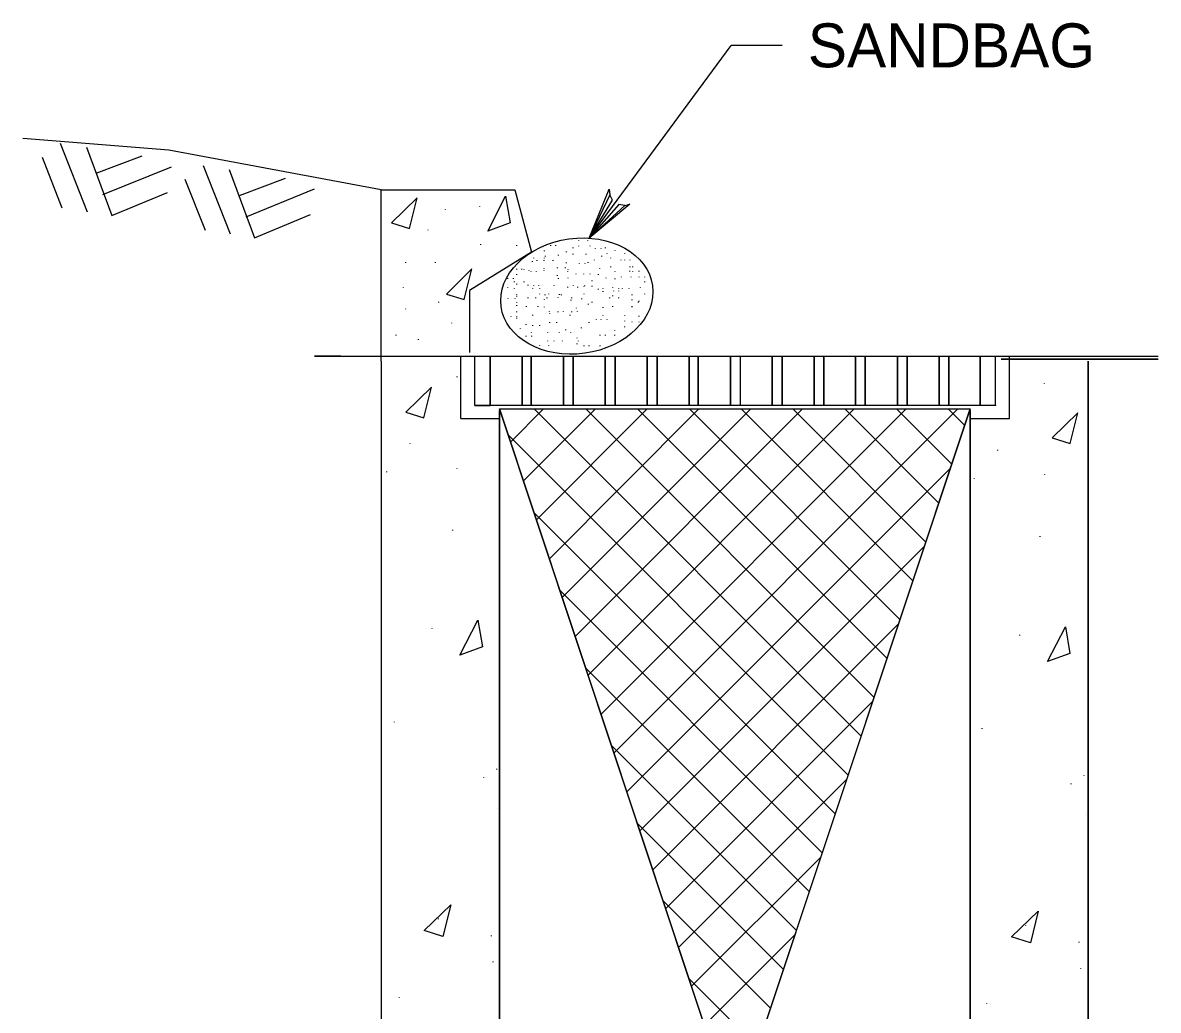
# Model space of a CAD drawing. Extents: x 636183 to 639890, y 299162 to 300538.
# Drawn here: x 636959.6 to 637037.2, y 299647.7 to 299715.1 of the extents above; entities that cross this region are included whole.
import ezdxf

# ---------------------------------------------------------------- set-up
doc = ezdxf.new("R2010")
doc.units = 0
doc.layers.add('1', color=7, linetype='Continuous')
doc.layers.add('Default', color=7, linetype='Continuous')

msp = doc.modelspace()

# ---------------------------------------------------------------- linework, layer by layer
at = {"layer": '1'}
for p, q in [((636979.564, 299692.303), (636990.512, 299692.303)), ((636990.512, 299688.945), (636990.512, 299692.303)), ((637026.049, 299692.303), (637037.172, 299692.303)), ((637026.049, 299688.945), (637026.049, 299692.303)), ((637027.018, 299688.046), (637027.018, 299692.303)), ((637026.049, 299688.945), (636990.512, 299688.945)), ((636992.191, 299688.701), (637008.245, 299640.467)), ((636992.943, 299686.441), (636995.202, 299688.701)), ((636993.826, 299683.789), (636998.738, 299688.701)), ((637016.885, 299666.366), (636994.55, 299688.701)), ((636994.709, 299681.136), (637002.273, 299688.701)), ((636995.592, 299678.483), (637005.809, 299688.701)), ((636996.475, 299675.831), (637009.344, 299688.701)), ((636997.358, 299673.178), (637012.88, 299688.701)), ((637017.769, 299669.017), (636998.085, 299688.701)), ((636998.24, 299670.526), (637016.415, 299688.701)), ((636999.123, 299667.873), (637019.951, 299688.701)), ((637000.006, 299665.22), (637023.486, 299688.701)), ((637018.653, 299671.668), (637001.621, 299688.701)), ((637019.538, 299674.319), (637005.156, 299688.701)), ((637008.245, 299640.467), (637024.335, 299688.701)), ((637020.422, 299676.97), (637008.692, 299688.701)), ((637021.306, 299679.621), (637012.227, 299688.701)), ((637022.191, 299682.273), (637015.763, 299688.701)), ((637023.075, 299684.924), (637019.298, 299688.701)), ((637023.959, 299687.575), (637022.834, 299688.701)), ((637016, 299663.714), (636992.778, 299686.936)), ((637000.889, 299662.568), (637022.99, 299684.669)), ((637015.116, 299661.063), (636994.542, 299681.637)), ((637001.772, 299659.915), (637021.22, 299679.363)), ((637014.231, 299658.412), (636996.306, 299676.337)), ((637002.655, 299657.263), (637019.451, 299674.058)), ((637013.347, 299655.761), (636998.07, 299671.038)), ((637003.538, 299654.61), (637017.681, 299668.753)), ((637012.463, 299653.11), (636999.834, 299665.739)), ((637004.421, 299651.957), (637015.911, 299663.448)), ((637011.578, 299650.459), (637001.598, 299660.439)), ((637005.304, 299649.305), (637014.142, 299658.142)), ((637010.694, 299647.807), (637003.362, 299655.14)), ((637006.187, 299646.652), (637012.372, 299652.837)), ((637009.81, 299645.156), (637005.126, 299649.84))]:
    msp.add_line(p, q, dxfattribs=at)
msp.add_lwpolyline([(636992.191, 299688.701), (637024.335, 299688.701), (637008.245, 299640.467)], close=True, dxfattribs=at)
at = {"layer": 'Default'}
for p, q in [((636998.32, 299700.357), (637007.997, 299713.513)), ((637011.495, 299713.513), (637007.997, 299713.513)), ((636962.187, 299706.84), (636964.039, 299702.154)), ((636962.187, 299706.84), (636964.039, 299702.154)), ((636963.989, 299706.561), (636965.717, 299701.893)), ((636963.989, 299706.561), (636965.717, 299701.893)), ((636960.953, 299705.894), (636962.31, 299702.422)), ((636960.953, 299705.894), (636962.31, 299702.422)), ((636964.65, 299704.789), (636967.791, 299705.971)), ((636964.65, 299704.789), (636967.791, 299705.971)), ((636965.106, 299703.328), (636969.8, 299705.229)), ((636965.106, 299703.328), (636969.8, 299705.229)), ((636971.963, 299705.323), (636973.79, 299700.641)), ((636971.963, 299705.323), (636973.79, 299700.641)), ((636973.741, 299705.047), (636975.469, 299700.38)), ((636973.741, 299705.047), (636975.469, 299700.38)), ((636970.705, 299704.381), (636972.087, 299700.905)), ((636970.705, 299704.381), (636972.087, 299700.905)), ((636974.426, 299703.272), (636977.568, 299704.454)), ((636974.426, 299703.272), (636977.568, 299704.454)), ((636965.717, 299701.893), (636969.528, 299703.476)), ((636965.717, 299701.893), (636969.528, 299703.476)), ((636974.882, 299701.811), (636979.552, 299703.716)), ((636974.882, 299701.811), (636979.552, 299703.716)), ((636986.574, 299703.119), (636984.825, 299701.405)), ((636986.049, 299701.02), (636986.574, 299703.119)), ((636991.385, 299700.833), (636992.61, 299703.212)), ((636992.61, 299703.212), (636992.924, 299701.393)), ((636975.469, 299700.38), (636979.28, 299701.963)), ((636975.469, 299700.38), (636979.28, 299701.963)), ((636988.506, 299702.286), (636988.506, 299702.321)), ((636990.854, 299702.485), (636990.854, 299702.519)), ((636984.825, 299701.405), (636986.049, 299701.02)), ((636992.924, 299701.393), (636991.385, 299700.833)), ((636987.316, 299700.897), (636987.316, 299700.932)), ((636990.92, 299699.906), (636990.92, 299699.941)), ((636993.367, 299699.839), (636993.367, 299699.874)), ((636995.268, 299699.476), (636995.268, 299699.511)), ((636995.697, 299699.839), (636995.697, 299699.874)), ((636996.028, 299699.839), (636996.028, 299699.874)), ((636996.028, 299699.839), (636996.028, 299699.874)), ((636997.218, 299699.674), (636997.218, 299699.709)), ((636997.218, 299699.674), (636997.218, 299699.709)), ((636997.615, 299700.17), (636997.615, 299700.205)), ((636997.615, 299700.17), (636997.615, 299700.205)), ((636997.615, 299699.806), (636997.615, 299699.841)), ((636997.615, 299699.806), (636997.615, 299699.841)), ((636998.21, 299700.17), (636998.21, 299700.205)), ((636998.376, 299699.806), (636998.376, 299699.841)), ((636998.376, 299699.806), (636998.376, 299699.841)), ((636998.739, 299699.641), (636998.739, 299699.676)), ((636999.136, 299699.641), (636999.136, 299699.676)), ((636999.434, 299699.674), (636999.434, 299699.709)), ((637000.095, 299699.509), (637000.095, 299699.544)), ((637000.095, 299699.509), (637000.095, 299699.544)), ((636985.795, 299698.682), (636985.795, 299698.717)), ((636987.812, 299698.682), (636987.812, 299698.717)), ((636994.441, 299698.748), (636994.441, 299698.783)), ((636994.54, 299698.98), (636994.54, 299699.015)), ((636994.772, 299698.815), (636994.772, 299698.849)), ((636994.772, 299698.815), (636994.772, 299698.849)), ((636995.235, 299698.815), (636995.235, 299698.849)), ((636995.268, 299698.98), (636995.268, 299699.015)), ((636995.334, 299699.112), (636995.334, 299699.147)), ((636995.863, 299698.815), (636995.863, 299698.849)), ((636996.227, 299699.178), (636996.227, 299699.213)), ((636996.227, 299699.178), (636996.227, 299699.213)), ((636996.227, 299699.178), (636996.227, 299699.213)), ((636996.756, 299699.41), (636996.756, 299699.445)), ((636997.218, 299699.244), (636997.218, 299699.279)), ((636998.111, 299699.244), (636998.111, 299699.279)), ((636998.243, 299698.682), (636998.243, 299698.717)), ((636998.673, 299698.848), (636998.673, 299698.882)), ((636999.169, 299699.112), (636999.169, 299699.147)), ((636999.533, 299699.277), (636999.533, 299699.312)), ((636999.797, 299698.98), (636999.797, 299699.015)), ((637000.492, 299698.848), (637000.492, 299698.882)), ((637000.492, 299698.848), (637000.492, 299698.882)), ((637000.492, 299698.848), (637000.492, 299698.882)), ((637000.756, 299699.277), (637000.756, 299699.312)), ((637000.756, 299698.848), (637000.756, 299698.882)), ((637001.12, 299698.848), (637001.12, 299698.882)), ((636990.31, 299698.259), (636988.561, 299696.545)), ((636989.785, 299696.16), (636990.31, 299698.259)), ((636993.383, 299698.219), (636993.383, 299698.254)), ((636993.714, 299698.219), (636993.714, 299698.254)), ((636993.879, 299698.186), (636993.879, 299698.221)), ((636994.21, 299698.12), (636994.21, 299698.155)), ((636994.21, 299698.12), (636994.21, 299698.155)), ((636994.342, 299698.054), (636994.342, 299698.089)), ((636994.706, 299698.054), (636994.706, 299698.089)), ((636995.235, 299698.252), (636995.235, 299698.287)), ((636995.235, 299698.252), (636995.235, 299698.287)), ((636995.235, 299698.12), (636995.235, 299698.155)), ((636996.16, 299698.319), (636996.16, 299698.353)), ((636996.689, 299698.319), (636996.689, 299698.353)), ((636996.756, 299698.649), (636996.756, 299698.684)), ((636996.855, 299698.054), (636996.855, 299698.089)), ((636996.855, 299698.054), (636996.855, 299698.089)), ((636996.888, 299698.186), (636996.888, 299698.221)), ((636997.417, 299697.889), (636997.417, 299697.924)), ((636997.648, 299698.616), (636997.648, 299698.651)), ((636997.648, 299698.616), (636997.648, 299698.651)), ((636997.946, 299697.889), (636997.946, 299697.924)), ((636998.045, 299698.616), (636998.045, 299698.651)), ((636998.045, 299698.616), (636998.045, 299698.651)), ((636998.376, 299697.889), (636998.376, 299697.924)), ((636998.376, 299697.889), (636998.376, 299697.924)), ((636999.037, 299698.285), (636999.037, 299698.32)), ((636999.797, 299698.385), (636999.797, 299698.42)), ((637000.095, 299698.054), (637000.095, 299698.089)), ((637001.087, 299698.087), (637001.087, 299698.122)), ((637001.12, 299698.385), (637001.12, 299698.42)), ((637001.285, 299698.385), (637001.285, 299698.42)), ((637001.285, 299698.054), (637001.285, 299698.089)), ((637001.715, 299698.087), (637001.715, 299698.122)), ((636992.755, 299697.591), (636992.755, 299697.626)), ((636993.152, 299697.591), (636993.152, 299697.626)), ((636993.152, 299697.591), (636993.152, 299697.626)), ((636993.218, 299697.36), (636993.218, 299697.395)), ((636993.383, 299697.856), (636993.383, 299697.891)), ((636993.383, 299697.194), (636993.383, 299697.229)), ((636993.383, 299697.194), (636993.383, 299697.229)), ((636993.879, 299697.36), (636993.879, 299697.395)), ((636993.879, 299697.36), (636993.879, 299697.395)), ((636994.144, 299697.128), (636994.144, 299697.163)), ((636994.144, 299697.128), (636994.144, 299697.163)), ((636996.16, 299697.79), (636996.16, 299697.824)), ((636996.16, 299697.79), (636996.16, 299697.824)), ((636996.227, 299697.591), (636996.227, 299697.626)), ((636996.888, 299697.624), (636996.888, 299697.659)), ((636998.508, 299697.426), (636998.508, 299697.461)), ((636998.938, 299697.856), (636998.938, 299697.891)), ((636999.467, 299697.624), (636999.467, 299697.659)), ((637000.095, 299697.558), (637000.095, 299697.593)), ((637000.525, 299697.69), (637000.525, 299697.725)), ((637001.186, 299697.69), (637001.186, 299697.725)), ((637001.715, 299697.69), (637001.715, 299697.725)), ((637002.112, 299697.69), (637002.112, 299697.725)), ((637002.112, 299697.36), (637002.112, 299697.395)), ((636985.63, 299696.963), (636985.63, 299696.998)), ((636988.561, 299696.545), (636989.785, 299696.16)), ((636992.755, 299696.963), (636992.755, 299696.998)), ((636992.755, 299696.963), (636992.755, 299696.998)), ((636992.755, 299696.963), (636992.755, 299696.998)), ((636993.218, 299696.897), (636993.218, 299696.932)), ((636993.218, 299696.897), (636993.218, 299696.932)), ((636993.383, 299696.467), (636993.383, 299696.502)), ((636993.383, 299696.467), (636993.383, 299696.502)), ((636993.383, 299696.368), (636993.383, 299696.403)), ((636994.474, 299696.897), (636994.474, 299696.932)), ((636994.54, 299697.095), (636994.54, 299697.13)), ((636994.871, 299697.095), (636994.871, 299697.13)), ((636994.937, 299696.897), (636994.937, 299696.932)), ((636994.937, 299696.533), (636994.937, 299696.568)), ((636995.301, 299696.467), (636995.301, 299696.502)), ((636995.565, 299696.533), (636995.565, 299696.568)), ((636995.929, 299697.095), (636995.929, 299697.13)), ((636995.929, 299697.095), (636995.929, 299697.13)), ((636996.293, 299696.5), (636996.293, 299696.535)), ((636996.425, 299696.467), (636996.425, 299696.502)), ((636996.855, 299696.996), (636996.855, 299697.031)), ((636997.251, 299697.095), (636997.251, 299697.13)), ((636997.549, 299696.996), (636997.549, 299697.031)), ((636997.549, 299696.996), (636997.549, 299697.031)), ((636997.979, 299697.029), (636997.979, 299697.064)), ((636997.979, 299696.533), (636997.979, 299696.568)), ((636997.979, 299696.533), (636997.979, 299696.568)), ((636998.012, 299697.095), (636998.012, 299697.13)), ((636998.508, 299697.062), (636998.508, 299697.097)), ((636998.938, 299696.864), (636998.938, 299696.899)), ((636999.268, 299696.897), (636999.268, 299696.932)), ((636999.268, 299696.698), (636999.268, 299696.733)), ((636999.93, 299696.963), (636999.93, 299696.998)), ((636999.93, 299696.401), (636999.93, 299696.436)), ((636999.996, 299696.732), (636999.996, 299696.766)), ((637000.326, 299696.897), (637000.326, 299696.932)), ((637000.326, 299696.732), (637000.326, 299696.766)), ((637000.591, 299696.897), (637000.591, 299696.932)), ((637001.054, 299696.897), (637001.054, 299696.932)), ((637001.252, 299696.467), (637001.252, 299696.502)), ((637001.252, 299696.467), (637001.252, 299696.502)), ((637001.814, 299696.963), (637001.814, 299696.998)), ((637002.112, 299696.533), (637002.112, 299696.568)), ((637002.112, 299696.533), (637002.112, 299696.568)), ((636988.043, 299695.971), (636988.043, 299696.006)), ((636992.788, 299696.236), (636992.788, 299696.27)), ((636993.251, 299696.236), (636993.251, 299696.27)), ((636993.383, 299695.938), (636993.383, 299695.973)), ((636993.383, 299695.74), (636993.383, 299695.775)), ((636994.044, 299695.673), (636994.044, 299695.708)), ((636994.144, 299696.269), (636994.144, 299696.304)), ((636994.673, 299696.269), (636994.673, 299696.304)), ((636994.838, 299695.673), (636994.838, 299695.708)), ((636995.268, 299696.169), (636995.268, 299696.204)), ((636995.268, 299695.64), (636995.268, 299695.675)), ((636995.433, 299696.269), (636995.433, 299696.304)), ((636996.193, 299696.302), (636996.193, 299696.337)), ((636997.086, 299696.103), (636997.086, 299696.138)), ((636997.119, 299696.269), (636997.119, 299696.304)), ((636997.45, 299695.574), (636997.45, 299695.609)), ((636997.814, 299696.202), (636997.814, 299696.237)), ((636997.814, 299696.202), (636997.814, 299696.237)), ((636998.276, 299695.839), (636998.276, 299695.874)), ((636998.508, 299695.971), (636998.508, 299696.006)), ((636999.268, 299695.607), (636999.268, 299695.642)), ((636999.731, 299696.269), (636999.731, 299696.304)), ((636999.93, 299695.673), (636999.93, 299695.708)), ((637000.326, 299696.269), (637000.326, 299696.304)), ((637001.252, 299696.136), (637001.252, 299696.171)), ((637001.252, 299695.673), (637001.252, 299695.708)), ((637001.252, 299695.64), (637001.252, 299695.675)), ((637001.682, 299695.971), (637001.682, 299696.006)), ((637001.715, 299696.037), (637001.715, 299696.072)), ((636985.795, 299695.508), (636985.795, 299695.543)), ((636992.986, 299694.979), (636992.986, 299695.014)), ((636992.986, 299694.979), (636992.986, 299695.014)), ((636992.986, 299694.979), (636992.986, 299695.014)), ((636993.383, 299695.31), (636993.383, 299695.345)), ((636993.383, 299695.31), (636993.383, 299695.345)), ((636993.383, 299694.979), (636993.383, 299695.014)), ((636993.383, 299694.88), (636993.383, 299694.915)), ((636994.474, 299695.078), (636994.474, 299695.113)), ((636995.598, 299695.343), (636995.598, 299695.378)), ((636995.631, 299695.211), (636995.631, 299695.246)), ((636996.193, 299695.31), (636996.193, 299695.345)), ((636996.193, 299695.31), (636996.193, 299695.345)), ((636996.557, 299695.343), (636996.557, 299695.378)), ((636997.02, 299695.078), (636997.02, 299695.113)), ((636997.119, 299695.31), (636997.119, 299695.345)), ((636997.516, 299695.343), (636997.516, 299695.378)), ((636999.268, 299695.045), (636999.268, 299695.08)), ((637000.756, 299695.045), (637000.756, 299695.08)), ((637001.715, 299695.012), (637001.715, 299695.047)), ((636988.936, 299694.549), (636988.936, 299694.584)), ((636993.614, 299694.186), (636993.614, 299694.221)), ((636994.011, 299694.45), (636994.011, 299694.485)), ((636994.011, 299694.45), (636994.011, 299694.485)), ((636994.474, 299694.384), (636994.474, 299694.419)), ((636994.937, 299694.384), (636994.937, 299694.419)), ((636995.631, 299694.582), (636995.631, 299694.617)), ((636996.094, 299694.582), (636996.094, 299694.617)), ((636996.722, 299694.086), (636996.722, 299694.121)), ((636997.78, 299694.219), (636997.78, 299694.254)), ((636998.31, 299694.582), (636998.31, 299694.617)), ((636998.31, 299694.582), (636998.31, 299694.617)), ((636998.805, 299694.781), (636998.805, 299694.816)), ((636999.136, 299694.781), (636999.136, 299694.816)), ((636999.533, 299694.781), (636999.533, 299694.816)), ((637000.062, 299694.053), (637000.062, 299694.088)), ((637000.062, 299694.053), (637000.062, 299694.088)), ((637000.756, 299694.682), (637000.756, 299694.717)), ((637000.756, 299694.285), (637000.756, 299694.32)), ((637000.756, 299694.285), (637000.756, 299694.32)), ((637001.252, 299694.615), (637001.252, 299694.65)), ((637001.715, 299694.615), (637001.715, 299694.65)), ((636985.134, 299693.723), (636985.134, 299693.758)), ((636986.655, 299693.425), (636986.655, 299693.46)), ((636994.011, 299693.657), (636994.011, 299693.692)), ((636994.011, 299693.657), (636994.011, 299693.692)), ((636994.011, 299693.657), (636994.011, 299693.692)), ((636994.011, 299693.657), (636994.011, 299693.692)), ((636994.375, 299693.888), (636994.375, 299693.923)), ((636994.375, 299693.888), (636994.375, 299693.923)), ((636994.408, 299693.657), (636994.408, 299693.692)), ((636995.499, 299693.888), (636995.499, 299693.923)), ((636995.499, 299693.326), (636995.499, 299693.361)), ((636995.929, 299693.326), (636995.929, 299693.361)), ((636995.929, 299693.326), (636995.929, 299693.361)), ((636996.293, 299693.888), (636996.293, 299693.923)), ((636996.491, 299693.326), (636996.491, 299693.361)), ((636997.053, 299693.888), (636997.053, 299693.923)), ((636997.483, 299693.524), (636997.483, 299693.559)), ((636997.483, 299693.524), (636997.483, 299693.559)), ((636997.582, 299693.326), (636997.582, 299693.361)), ((636999.07, 299693.723), (636999.07, 299693.758)), ((636999.434, 299693.723), (636999.434, 299693.758)), ((637000.062, 299693.723), (637000.062, 299693.758)), ((636994.937, 299693.028), (636994.937, 299693.063)), ((636995.565, 299693.028), (636995.565, 299693.063)), ((636997.483, 299693.128), (636997.483, 299693.163)), ((636997.979, 299692.995), (636997.979, 299693.03)), ((636997.979, 299692.995), (636997.979, 299693.03)), ((636998.31, 299692.995), (636998.31, 299693.03)), ((636999.07, 299692.995), (636999.07, 299693.03)), ((636980.474, 299692.303), (636979.564, 299692.303)), ((636979.564, 299692.303), (636980.474, 299692.303)), ((636980.474, 299692.303), (636979.564, 299692.303)), ((636979.564, 299692.303), (636980.474, 299692.303)), ((636981.348, 299692.303), (636980.474, 299692.303)), ((636980.474, 299692.303), (636981.348, 299692.303)), ((636981.348, 299692.303), (636980.474, 299692.303)), ((636980.474, 299692.303), (636981.348, 299692.303)), ((636984.111, 299691.953), (636984.111, 299611.541)), ((636989.543, 299688.046), (636989.543, 299692.303)), ((636990.512, 299692.303), (637026.049, 299692.303)), ((636991.561, 299688.945), (636991.561, 299692.303)), ((636991.561, 299692.303), (636991.561, 299688.945)), ((636993.73, 299688.945), (636993.73, 299692.303)), ((636993.73, 299692.303), (636993.73, 299688.945)), ((636993.73, 299688.945), (636993.73, 299692.303)), ((636994.36, 299688.945), (636994.36, 299692.303)), ((636994.36, 299692.303), (636994.36, 299688.945)), ((636996.563, 299688.945), (636996.563, 299692.303)), ((636996.563, 299692.303), (636996.563, 299688.945)), ((636996.563, 299688.945), (636996.563, 299692.303)), ((636997.228, 299688.945), (636997.228, 299692.303)), ((636997.228, 299692.303), (636997.228, 299688.945)), ((636999.396, 299688.945), (636999.396, 299692.303)), ((636999.396, 299692.303), (636999.396, 299688.945)), ((636999.396, 299688.945), (636999.396, 299692.303)), ((637000.096, 299688.945), (637000.096, 299692.303)), ((637000.096, 299692.303), (637000.096, 299688.945)), ((637002.264, 299692.303), (637002.264, 299688.945)), ((637002.264, 299688.945), (637002.264, 299692.303)), ((637002.264, 299692.303), (637002.264, 299688.945)), ((637002.964, 299688.945), (637002.964, 299692.303)), ((637002.964, 299692.303), (637002.964, 299688.945)), ((637005.133, 299688.945), (637005.133, 299692.303)), ((637005.133, 299692.303), (637005.133, 299688.945)), ((637005.133, 299688.945), (637005.133, 299692.303)), ((637005.762, 299688.945), (637005.762, 299692.303)), ((637005.762, 299692.303), (637005.762, 299688.945)), ((637007.966, 299688.945), (637007.966, 299692.303)), ((637007.966, 299692.303), (637007.966, 299688.945)), ((637007.966, 299688.945), (637007.966, 299692.303)), ((637008.63, 299692.303), (637008.63, 299688.945)), ((637008.63, 299692.303), (637008.63, 299688.945)), ((637010.799, 299688.945), (637010.799, 299692.303)), ((637010.799, 299692.303), (637010.799, 299688.945)), ((637010.799, 299688.945), (637010.799, 299692.303)), ((637011.498, 299692.303), (637011.498, 299688.945)), ((637011.498, 299688.945), (637011.498, 299692.303)), ((637013.667, 299688.945), (637013.667, 299692.303)), ((637013.667, 299692.303), (637013.667, 299688.945)), ((637013.667, 299688.945), (637013.667, 299692.303)), ((637014.331, 299692.303), (637014.331, 299688.945)), ((637014.331, 299688.945), (637014.331, 299692.303)), ((637016.5, 299692.303), (637016.5, 299688.945)), ((637016.5, 299688.945), (637016.5, 299692.303)), ((637016.5, 299692.303), (637016.5, 299688.945)), ((637017.165, 299692.303), (637017.165, 299688.945)), ((637017.165, 299688.945), (637017.165, 299692.303)), ((637019.368, 299688.945), (637019.368, 299692.303)), ((637019.368, 299692.303), (637019.368, 299688.945)), ((637019.368, 299688.945), (637019.368, 299692.303)), ((637020.033, 299692.303), (637020.033, 299688.945)), ((637020.033, 299688.945), (637020.033, 299692.303)), ((637022.201, 299692.303), (637022.201, 299688.945)), ((637022.201, 299688.945), (637022.201, 299692.303)), ((637022.201, 299692.303), (637022.201, 299688.945)), ((637022.866, 299692.303), (637022.866, 299688.945)), ((637022.866, 299688.945), (637022.866, 299692.303)), ((637025, 299688.945), (637025, 299692.303)), ((637025, 299692.303), (637025, 299688.945)), ((637025, 299688.945), (637025, 299692.303)), ((637026.049, 299692.303), (637026.049, 299692.303)), ((637037.172, 299692.093), (637026.434, 299692.093)), ((637026.434, 299692.093), (637037.172, 299692.093)), ((637032.38, 299611.541), (637032.38, 299691.953)), ((637032.38, 299691.953), (637032.38, 299611.541)), ((637032.38, 299611.541), (637032.38, 299691.953)), ((636987.549, 299690.191), (636985.8, 299688.477)), ((636987.025, 299688.093), (636987.549, 299690.191)), ((636989.289, 299690.875), (636989.289, 299690.91)), ((637029.407, 299690.437), (637029.407, 299690.472)), ((636992.191, 299688.945), (636990.512, 299688.945)), ((636990.512, 299688.945), (636991.561, 299688.945)), ((636991.561, 299688.945), (636990.512, 299688.945)), ((636992.226, 299688.631), (636992.191, 299688.596)), ((637026.049, 299688.945), (637026.049, 299688.91)), ((636985.8, 299688.477), (636987.025, 299688.093)), ((636989.543, 299688.046), (636992.155, 299688.046)), ((636992.191, 299688.596), (636992.191, 299619.586)), ((636992.191, 299619.586), (636992.191, 299688.596)), ((636992.191, 299688.596), (636992.191, 299619.586)), ((637024.335, 299619.586), (637024.335, 299688.596)), ((637024.335, 299688.596), (637024.335, 299619.586)), ((637024.335, 299619.586), (637024.335, 299688.596)), ((637024.335, 299688.046), (637027.018, 299688.046)), ((637031.681, 299688.443), (637029.932, 299686.729)), ((637031.156, 299686.345), (637031.681, 299688.443)), ((636986.091, 299686.313), (636986.091, 299686.348)), ((637029.932, 299686.729), (637031.156, 299686.345)), ((637026.21, 299685.876), (637026.21, 299685.911)), ((636984.483, 299684.425), (636984.483, 299684.39)), ((636989.309, 299684.635), (636989.309, 299684.669)), ((637024.601, 299683.987), (637024.601, 299683.952)), ((637029.427, 299684.197), (637029.427, 299684.232)), ((636988.974, 299680.452), (636988.974, 299680.417)), ((637029.092, 299680.014), (637029.092, 299679.979)), ((636989.484, 299671.903), (636990.709, 299674.281)), ((636990.709, 299674.281), (636991.023, 299672.462)), ((636987.596, 299673.687), (636987.596, 299673.722)), ((637027.714, 299673.249), (637027.714, 299673.284)), ((637029.602, 299671.465), (637030.827, 299673.843)), ((637030.827, 299673.843), (637031.141, 299672.025)), ((636991.023, 299672.462), (636989.484, 299671.903)), ((637031.141, 299672.025), (637029.602, 299671.465)), ((636985.007, 299667.356), (636985.007, 299667.321)), ((637025.125, 299666.918), (637025.125, 299666.883)), ((636992.003, 299664.103), (636992.003, 299664.138)), ((636991.093, 299663.578), (636991.093, 299663.543)), ((637031.211, 299663.14), (637031.211, 299663.105)), ((637032.121, 299663.665), (637032.121, 299663.7)), ((636992.073, 299661.445), (636992.073, 299661.445)), ((637032.191, 299661.007), (637032.191, 299661.007)), ((636987.036, 299653.12), (636988.855, 299654.869)), ((636988.855, 299654.869), (636988.33, 299652.7)), ((636988.015, 299653.89), (636988.015, 299653.925)), ((637027.154, 299652.682), (637028.973, 299654.431)), ((637028.973, 299654.431), (637028.448, 299652.262)), ((636988.33, 299652.7), (636987.036, 299653.12)), ((637028.133, 299653.452), (637028.133, 299653.487)), ((636991.653, 299652.735), (636991.653, 299652.77)), ((637028.448, 299652.262), (637027.154, 299652.682)), ((637031.771, 299652.298), (637031.771, 299652.332)), ((636991.758, 299650.951), (636991.758, 299650.987)), ((637031.876, 299650.514), (637031.876, 299650.549)), ((636985.357, 299648.538), (636985.357, 299648.573)), ((637025.475, 299648.1), (637025.475, 299648.135))]:
    msp.add_line(p, q, dxfattribs=at)
for points in [[(636984.111, 299703.658), (636969.619, 299706.369), (636959.634, 299707.163)], [(636984.111, 299691.953), (636984.111, 299703.658), (636993.243, 299703.658), (636994.367, 299699.393), (636990.135, 299696.781), (636990.135, 299692.549)], [(637000.748, 299702.583), (637001.088, 299702.667), (636998.32, 299700.357), (637000.748, 299702.583), (637000.332, 299702.645), (636998.32, 299700.357), (636999.906, 299702.951), (636999.712, 299703.32), (636998.32, 299700.357), (636999.675, 299703.698), (636999.712, 299703.32)]]:
    msp.add_lwpolyline(points, dxfattribs=at)
msp.add_ellipse((636997.469, 299696.402), major_axis=(-5.169, -0.717), ratio=0.755338, dxfattribs=at)

# ---------------------------------------------------------------- texts
msp.add_text('SANDBAG', height=2.998, dxfattribs=at).set_placement((637013.244, 299712.014))

doc.saveas('drawing.dxf')
